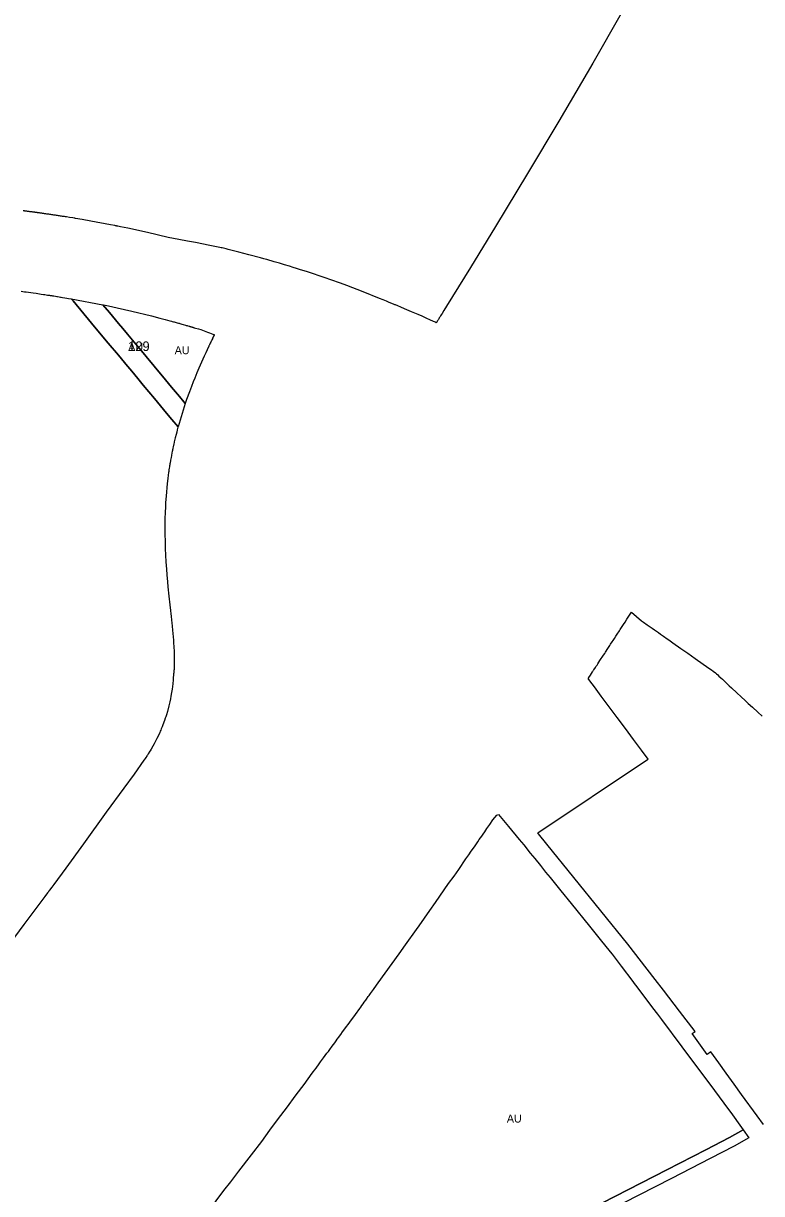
# Model space of a CAD drawing. Extents: x -537068 to -534056, y -1176840 to -1172401.
# Drawn here: x -536541 to -536080, y -1174949 to -1174218 of the extents above; entities that cross this region are included whole.
import ezdxf

# ---------------------------------------------------------------- set-up
doc = ezdxf.new("R2010")
doc.units = 0
for name, color, linetype in [('90710023', 7, 'Continuous'), ('90750013', 7, 'Continuous'), ('90750023', 7, 'Continuous'), ('ID_navrh', 7, 'Continuous')]:
    doc.layers.add(name, color=color, linetype=linetype)

msp = doc.modelspace()

# ---------------------------------------------------------------- linework, layer by layer
at = {"layer": '90710023'}
msp.add_lwpolyline([(-536179.07, -1174955.11), (-536138.87, -1174934.4), (-536114.61, -1174921.9), (-536099.73, -1174914.23), (-536091.18, -1174909.41), (-536087.7, -1174914.34), (-536096.88, -1174919.51), (-536111.86, -1174927.23), (-536136.12, -1174939.73), (-536176.32, -1174960.44)], dxfattribs=at)
at = {"layer": '90750013'}
for points in [[(-536167.39, -1174211.76), (-536185.2, -1174242.92), (-536206.47, -1174279.11), (-536226.04, -1174311.88), (-536245.85, -1174344.89), (-536261.5, -1174370.57), (-536276.47, -1174394.75), (-536278.12, -1174397.41), (-536279.32, -1174399.29), (-536279.8, -1174400.06), (-536280.27, -1174400.82), (-536280.79, -1174401.65), (-536281.05, -1174402.07), (-536281.38, -1174402.6), (-536281.6, -1174402.95), (-536281.78, -1174403.24), (-536282, -1174403.59), (-536282.28, -1174404.03), (-536282.44, -1174404.3), (-536282.64, -1174404.62), (-536282.76, -1174404.8), (-536282.77, -1174404.82), (-536282.78, -1174404.84), (-536282.79, -1174404.85), (-536282.8, -1174404.87), (-536282.83, -1174404.91), (-536282.88, -1174404.99), (-536282.91, -1174405.04), (-536282.91, -1174405.05), (-536282.92, -1174405.05), (-536282.92, -1174405.06), (-536283.5, -1174404.79), (-536283.99, -1174404.56), (-536284.74, -1174404.22), (-536287.03, -1174403.18), (-536288.89, -1174402.34), (-536291.82, -1174401.02), (-536294.29, -1174399.94), (-536298.38, -1174398.15), (-536302.76, -1174396.3), (-536305.03, -1174395.35), (-536307.03, -1174394.52), (-536307.46, -1174394.35), (-536308, -1174394.12), (-536308.4, -1174393.96), (-536308.82, -1174393.78), (-536309.68, -1174393.43), (-536310.21, -1174393.21), (-536310.75, -1174392.99), (-536312.38, -1174392.33), (-536313.99, -1174391.68), (-536316.07, -1174390.85), (-536318.46, -1174389.9), (-536328.56, -1174385.71), (-536338.75, -1174381.78), (-536342.81, -1174380.27), (-536348.81, -1174378.18), (-536352.24, -1174377.01), (-536355.46, -1174375.92), (-536360.21, -1174374.36), (-536363.95, -1174373.15), (-536367.71, -1174371.96), (-536370.22, -1174371.18), (-536372.29, -1174370.52), (-536374.68, -1174369.78), (-536377.82, -1174368.83), (-536380.84, -1174367.93), (-536384.28, -1174366.93), (-536388.73, -1174365.64), (-536389.74, -1174365.36), (-536390.66, -1174365.1), (-536392.72, -1174364.52), (-536400.1, -1174362.55), (-536406.21, -1174360.95), (-536409.68, -1174360.06), (-536412.92, -1174359.26), (-536414.22, -1174358.94), (-536415.89, -1174358.54), (-536416.64, -1174358.36), (-536417.29, -1174358.2), (-536418.11, -1174358.01), (-536424.41, -1174356.74), (-536433.4, -1174354.97), (-536438.38, -1174354.08), (-536443.72, -1174353.14), (-536450.5, -1174351.85), (-536463.41, -1174348.62), (-536475.59, -1174346.07), (-536480.22, -1174345.08), (-536481.74, -1174344.77), (-536482.41, -1174344.63), (-536482.72, -1174344.57), (-536483.35, -1174344.44), (-536483.81, -1174344.35), (-536486.52, -1174343.8), (-536498.74, -1174341.52), (-536504.04, -1174340.59), (-536508.25, -1174339.88), (-536508.8, -1174339.79), (-536508.97, -1174339.77), (-536509.01, -1174339.76), (-536509.03, -1174339.76), (-536509.04, -1174339.75), (-536509.05, -1174339.75), (-536509.06, -1174339.75), (-536509.07, -1174339.75), (-536509.98, -1174339.6), (-536512.13, -1174339.25), (-536513.97, -1174338.96), (-536514.58, -1174338.87), (-536515.19, -1174338.77), (-536515.8, -1174338.68), (-536516.41, -1174338.58), (-536517.03, -1174338.49), (-536517.64, -1174338.4), (-536518.25, -1174338.3), (-536518.86, -1174338.21), (-536519.47, -1174338.12), (-536520.08, -1174338.03), (-536520.69, -1174337.93), (-536521.3, -1174337.84), (-536521.91, -1174337.75), (-536522.52, -1174337.66), (-536523.13, -1174337.57), (-536523.74, -1174337.49), (-536524.35, -1174337.4), (-536524.96, -1174337.31), (-536525.57, -1174337.22), (-536526.18, -1174337.13), (-536526.79, -1174337.05), (-536527.09, -1174337), (-536527.4, -1174336.96), (-536527.7, -1174336.92), (-536528.01, -1174336.88), (-536528.31, -1174336.83), (-536528.62, -1174336.79), (-536528.92, -1174336.75), (-536529.22, -1174336.7), (-536529.53, -1174336.66), (-536529.83, -1174336.62), (-536530.14, -1174336.58), (-536530.44, -1174336.54), (-536530.75, -1174336.49), (-536531.05, -1174336.45), (-536531.35, -1174336.41), (-536531.66, -1174336.37), (-536531.96, -1174336.33), (-536532.26, -1174336.28), (-536532.57, -1174336.24), (-536532.87, -1174336.2), (-536533.18, -1174336.16), (-536533.48, -1174336.12), (-536533.78, -1174336.08), (-536534.09, -1174336.04), (-536534.39, -1174335.99), (-536534.69, -1174335.95), (-536535, -1174335.91), (-536535.3, -1174335.87), (-536535.6, -1174335.83), (-536535.91, -1174335.79), (-536536.21, -1174335.75), (-536536.51, -1174335.71), (-536536.82, -1174335.67), (-536537.12, -1174335.63), (-536537.42, -1174335.59), (-536537.73, -1174335.55), (-536538.03, -1174335.51), (-536538.33, -1174335.47), (-536538.63, -1174335.43), (-536538.94, -1174335.39), (-536539.24, -1174335.35), (-536539.54, -1174335.31), (-536539.85, -1174335.27), (-536540.15, -1174335.23), (-536540.45, -1174335.19), (-536540.75, -1174335.15), (-536541.06, -1174335.11)], [(-536542.24, -1174385.39), (-536540.21, -1174385.66), (-536539.04, -1174385.82), (-536537.59, -1174386.02), (-536536.14, -1174386.22), (-536534.69, -1174386.43), (-536532.95, -1174386.67), (-536531.8, -1174386.84), (-536529.78, -1174387.14), (-536528.33, -1174387.35), (-536527.47, -1174387.48), (-536526.6, -1174387.61), (-536525.74, -1174387.74), (-536525.17, -1174387.82), (-536524.59, -1174387.91), (-536524.02, -1174388), (-536523.16, -1174388.13), (-536522.58, -1174388.22), (-536521.72, -1174388.36), (-536520.86, -1174388.49), (-536520, -1174388.63), (-536519.43, -1174388.72), (-536518.57, -1174388.86), (-536517.72, -1174389), (-536517.14, -1174389.09), (-536516.34, -1174389.22), (-536514.86, -1174389.46), (-536513.65, -1174389.66), (-536512.58, -1174389.85), (-536510.97, -1174390.13), (-536509.84, -1174391.48), (-536503.16, -1174399.47), (-536495.28, -1174408.89), (-536487.81, -1174417.82), (-536481.51, -1174425.34), (-536477.7, -1174429.89), (-536476.74, -1174431.03), (-536473.17, -1174435.33), (-536469.4, -1174439.87), (-536465.96, -1174444.02), (-536462.53, -1174448.14), (-536458.89, -1174452.51), (-536451.43, -1174461.48), (-536448.09, -1174465.49), (-536444.22, -1174470.15), (-536444.29, -1174470.42), (-536444.7, -1174471.91), (-536445.09, -1174473.42), (-536445.48, -1174474.94), (-536445.99, -1174476.98), (-536446.6, -1174479.57), (-536446.96, -1174481.14), (-536447.06, -1174481.6), (-536447.27, -1174482.55), (-536447.44, -1174483.34), (-536447.48, -1174483.54), (-536447.5, -1174483.64), (-536447.53, -1174483.76), (-536447.54, -1174483.83), (-536447.56, -1174483.92), (-536447.57, -1174483.97), (-536447.59, -1174484.05), (-536447.6, -1174484.11), (-536447.62, -1174484.19), (-536447.63, -1174484.24), (-536447.65, -1174484.33), (-536447.66, -1174484.39), (-536447.68, -1174484.5), (-536447.7, -1174484.59), (-536447.71, -1174484.65), (-536447.72, -1174484.7), (-536447.73, -1174484.73), (-536447.73, -1174484.74), (-536447.73, -1174484.75), (-536447.74, -1174484.77), (-536447.74, -1174484.78), (-536447.76, -1174484.86), (-536447.78, -1174484.97), (-536447.9, -1174485.53), (-536448.06, -1174486.4), (-536448.4, -1174488.1), (-536448.6, -1174489.21), (-536448.92, -1174490.92), (-536449.25, -1174492.83), (-536449.25, -1174492.87), (-536449.26, -1174492.91), (-536449.26, -1174492.93), (-536449.26, -1174492.94), (-536449.27, -1174492.95), (-536449.28, -1174493.06), (-536449.29, -1174493.07), (-536449.29, -1174493.09), (-536449.29, -1174493.1), (-536449.29, -1174493.11), (-536449.29, -1174493.12), (-536449.3, -1174493.13), (-536449.3, -1174493.15), (-536449.3, -1174493.16), (-536449.3, -1174493.17), (-536449.31, -1174493.22), (-536449.32, -1174493.25), (-536449.32, -1174493.28), (-536449.32, -1174493.29), (-536449.33, -1174493.34), (-536449.33, -1174493.35), (-536449.33, -1174493.36), (-536449.34, -1174493.37), (-536449.34, -1174493.38), (-536449.34, -1174493.39), (-536449.34, -1174493.4), (-536449.34, -1174493.41), (-536449.35, -1174493.45), (-536449.35, -1174493.46), (-536449.36, -1174493.51), (-536449.37, -1174493.59), (-536449.38, -1174493.66), (-536449.4, -1174493.77), (-536449.44, -1174493.97), (-536449.48, -1174494.26), (-536449.54, -1174494.59), (-536449.58, -1174494.88), (-536449.63, -1174495.19), (-536449.75, -1174495.96), (-536449.9, -1174496.98), (-536450.06, -1174498.03), (-536450.16, -1174498.73), (-536450.38, -1174500.38), (-536450.65, -1174502.44), (-536451.02, -1174505.61), (-536451.29, -1174508.22), (-536451.53, -1174510.81), (-536451.75, -1174513.36), (-536452.02, -1174517.4), (-536452.16, -1174519.88), (-536452.33, -1174523.79), (-536452.43, -1174527.15), (-536452.5, -1174532.78), (-536452.48, -1174536.44), (-536452.35, -1174542.66), (-536452.23, -1174546.1), (-536452.04, -1174550.3), (-536451.8, -1174554.37), (-536451.47, -1174559.05), (-536451.2, -1174562.49), (-536450.82, -1174566.91), (-536450.52, -1174570.12), (-536449.94, -1174575.9), (-536449.37, -1174581.34), (-536448.98, -1174584.97), (-536448.76, -1174587.01), (-536448.61, -1174588.44), (-536448.34, -1174590.95), (-536448.17, -1174592.58), (-536447.96, -1174594.69), (-536447.71, -1174597.24), (-536447.53, -1174599.2), (-536447.34, -1174601.34), (-536447.17, -1174603.39), (-536447.01, -1174605.57), (-536446.9, -1174607.24), (-536446.83, -1174608.4), (-536446.75, -1174609.77), (-536446.69, -1174611.08), (-536446.65, -1174612.34), (-536446.61, -1174613.55), (-536446.59, -1174614.72), (-536446.57, -1174615.98), (-536446.58, -1174617.47), (-536446.58, -1174617.76), (-536446.59, -1174618.18), (-536446.6, -1174618.45), (-536446.6, -1174618.72), (-536446.62, -1174619.25), (-536446.63, -1174619.64), (-536446.65, -1174620.02), (-536446.67, -1174620.5), (-536446.69, -1174620.98), (-536446.71, -1174621.32), (-536446.74, -1174621.65), (-536446.75, -1174621.87), (-536446.77, -1174622.08), (-536446.78, -1174622.29), (-536446.81, -1174622.59), (-536446.83, -1174622.89), (-536446.85, -1174623.08), (-536446.92, -1174623.71), (-536446.93, -1174623.79), (-536446.94, -1174623.91), (-536446.94, -1174623.94), (-536446.95, -1174623.98), (-536446.95, -1174623.99), (-536446.95, -1174624), (-536446.95, -1174624.01), (-536446.95, -1174624.02), (-536446.95, -1174624.03), (-536446.95, -1174624.04), (-536446.96, -1174624.05), (-536446.96, -1174624.06), (-536446.96, -1174624.07), (-536446.96, -1174624.08), (-536446.96, -1174624.11), (-536446.96, -1174624.12), (-536446.97, -1174624.14), (-536446.97, -1174624.17), (-536446.98, -1174624.21), (-536446.98, -1174624.26), (-536446.98, -1174624.28), (-536446.99, -1174624.33), (-536447.04, -1174624.72), (-536447.07, -1174624.96), (-536447.15, -1174625.52), (-536447.22, -1174626.58), (-536447.32, -1174628.16), (-536447.54, -1174630.65), (-536447.97, -1174634.02), (-536448.26, -1174636.09), (-536448.64, -1174638.38), (-536448.99, -1174640.13), (-536449.34, -1174641.85), (-536449.92, -1174644.38), (-536450.88, -1174647.95), (-536451.52, -1174650.08), (-536451.93, -1174651.39), (-536452.21, -1174652.22), (-536452.72, -1174653.7), (-536453.67, -1174656.3), (-536453.91, -1174656.9), (-536454.16, -1174657.54), (-536454.33, -1174657.95), (-536454.7, -1174658.86), (-536455.01, -1174659.61), (-536455.33, -1174660.34), (-536455.65, -1174661.05), (-536455.91, -1174661.68), (-536457.41, -1174664.84), (-536459.2, -1174668.27), (-536459.91, -1174669.56), (-536461.07, -1174671.55), (-536461.7, -1174672.59), (-536461.84, -1174672.83), (-536462.79, -1174674.34), (-536462.9, -1174674.51), (-536463.37, -1174675.23), (-536463.47, -1174675.39), (-536463.5, -1174675.42), (-536463.51, -1174675.44), (-536463.59, -1174675.57), (-536463.63, -1174675.62), (-536463.75, -1174675.8), (-536464.35, -1174676.7), (-536464.52, -1174676.95), (-536464.62, -1174677.1), (-536465.57, -1174678.46), (-536471.74, -1174687.11), (-536478.01, -1174695.81), (-536489.05, -1174710.98), (-536503.23, -1174730.7), (-536514.37, -1174745.87), (-536521.87, -1174756.07), (-536523.15, -1174757.8), (-536524.44, -1174759.54), (-536524.56, -1174759.7), (-536524.74, -1174759.94), (-536524.78, -1174760), (-536524.81, -1174760.04), (-536524.82, -1174760.05), (-536524.82, -1174760.06), (-536524.83, -1174760.06), (-536524.83, -1174760.07), (-536524.84, -1174760.08), (-536524.85, -1174760.09), (-536524.86, -1174760.1), (-536524.86, -1174760.11), (-536524.87, -1174760.11), (-536524.87, -1174760.12), (-536524.88, -1174760.14), (-536524.89, -1174760.15), (-536524.9, -1174760.17), (-536524.93, -1174760.2), (-536524.95, -1174760.23), (-536524.96, -1174760.24), (-536524.99, -1174760.27), (-536525.03, -1174760.34), (-536525.06, -1174760.38), (-536525.09, -1174760.41), (-536525.1, -1174760.43), (-536525.12, -1174760.45), (-536525.14, -1174760.49), (-536525.17, -1174760.53), (-536525.2, -1174760.56), (-536525.22, -1174760.59), (-536525.29, -1174760.69), (-536525.32, -1174760.72), (-536525.37, -1174760.79), (-536525.44, -1174760.88), (-536525.56, -1174761.05), (-536525.68, -1174761.21), (-536527.39, -1174763.63), (-536540.49, -1174781.02), (-536546.4, -1174789.03)], [(-536078.52, -1174906.12), (-536082.49, -1174900.65), (-536092.2, -1174887.28), (-536096.81, -1174880.92), (-536101.82, -1174874.01), (-536106.55, -1174867.48), (-536111.47, -1174860.69), (-536113.67, -1174862.22), (-536123.18, -1174849.17), (-536121.32, -1174847.86), (-536131.09, -1174835.14), (-536141.08, -1174822.15), (-536146.22, -1174815.46), (-536151.19, -1174809), (-536163.27, -1174793.29), (-536213.79, -1174730.95), (-536219.11, -1174724.39), (-536219.53, -1174723.87), (-536152.25, -1174678.88), (-536150.59, -1174677.77), (-536154.85, -1174672.05), (-536159.67, -1174665.58), (-536164.83, -1174658.65), (-536169.92, -1174651.82), (-536174.9, -1174645.14), (-536179.96, -1174638.35), (-536184.2, -1174632.66), (-536187, -1174628.9), (-536188.1, -1174627.42), (-536187.87, -1174627.06), (-536187.29, -1174626.2), (-536187.05, -1174625.84), (-536186.67, -1174625.25), (-536185.3, -1174623.16), (-536185.09, -1174622.85), (-536184.9, -1174622.57), (-536184.7, -1174622.26), (-536184.47, -1174621.9), (-536184.15, -1174621.43), (-536183.9, -1174621.04), (-536183.59, -1174620.56), (-536183.18, -1174619.95), (-536182.54, -1174618.98), (-536182.04, -1174618.24), (-536181.41, -1174617.25), (-536180.7, -1174616.18), (-536179.9, -1174614.97), (-536179.23, -1174613.94), (-536178.42, -1174612.69), (-536177.76, -1174611.69), (-536177.24, -1174610.91), (-536175.77, -1174608.64), (-536175.32, -1174607.98), (-536174.89, -1174607.3), (-536174.53, -1174606.75), (-536174.02, -1174605.97), (-536173.08, -1174604.53), (-536172.46, -1174603.58), (-536171.61, -1174602.29), (-536170.74, -1174600.94), (-536169.96, -1174599.75), (-536169.51, -1174599.07), (-536168.91, -1174598.14), (-536168.51, -1174597.52), (-536168.01, -1174596.73), (-536167.18, -1174595.51), (-536165.99, -1174593.67), (-536165.06, -1174592.19), (-536163.84, -1174590.35), (-536162.61, -1174588.43), (-536161.02, -1174586), (-536154.69, -1174591.35), (-536153.43, -1174592.24), (-536151.14, -1174593.83), (-536148.12, -1174595.95), (-536146.68, -1174596.96), (-536144.22, -1174598.71), (-536142.93, -1174599.59), (-536140.95, -1174601), (-536138.82, -1174602.51), (-536137.66, -1174603.31), (-536135.2, -1174605.08), (-536130.17, -1174608.6), (-536125.9, -1174611.57), (-536121.16, -1174614.93), (-536116.14, -1174618.45), (-536112.12, -1174621.27), (-536111.04, -1174622.04), (-536110.05, -1174622.73), (-536108.61, -1174623.75), (-536107.87, -1174624.42), (-536107.18, -1174625.1), (-536106.35, -1174625.83), (-536105.3, -1174626.86), (-536104.24, -1174627.86), (-536103.19, -1174628.87), (-536100.95, -1174630.96), (-536099.93, -1174631.93), (-536098.56, -1174633.22), (-536095.25, -1174636.35), (-536092.56, -1174638.79), (-536089.94, -1174641.13), (-536088.04, -1174642.95), (-536085.41, -1174645.3), (-536082.01, -1174648.5), (-536079.3, -1174650.88)], [(-536425.14, -1174960.28), (-536415.59, -1174947.33), (-536411.22, -1174941.83), (-536406.2, -1174935.2), (-536398.28, -1174925), (-536391.96, -1174916.59), (-536386.87, -1174909.63), (-536381.45, -1174902.35), (-536376.43, -1174895.8), (-536370.44, -1174887.54), (-536365.51, -1174880.99), (-536360.38, -1174874.04), (-536359.54, -1174872.92), (-536358.91, -1174872.07), (-536358.05, -1174870.93), (-536357.54, -1174870.19), (-536356.53, -1174868.82), (-536355.24, -1174867), (-536353.3, -1174864.49), (-536351.21, -1174861.58), (-536350.3, -1174860.39), (-536349.51, -1174859.28), (-536347.98, -1174857.21), (-536347.15, -1174856.04), (-536346.36, -1174854.99), (-536345.53, -1174853.83), (-536344.78, -1174852.84), (-536343.77, -1174851.45), (-536343.34, -1174850.86), (-536342.53, -1174849.75), (-536341.42, -1174848.25), (-536338.79, -1174844.63), (-536338.16, -1174843.75), (-536337.44, -1174842.77), (-536336.55, -1174841.54), (-536335.68, -1174840.44), (-536333.49, -1174837.29), (-536330.7, -1174833.51), (-536330.14, -1174832.7), (-536329.35, -1174831.62), (-536328.7, -1174830.71), (-536327.95, -1174829.68), (-536327.04, -1174828.44), (-536326.49, -1174827.68), (-536325.38, -1174826.13), (-536324.93, -1174825.53), (-536324.46, -1174824.88), (-536323.96, -1174824.17), (-536323.37, -1174823.37), (-536322.8, -1174822.56), (-536322.11, -1174821.6), (-536321.7, -1174821.05), (-536319.22, -1174817.54), (-536306.21, -1174799.45), (-536302.21, -1174793.69), (-536295.37, -1174784.2), (-536293.67, -1174781.82), (-536286.98, -1174772.33), (-536283.4, -1174767.33), (-536275.22, -1174755.48), (-536271.83, -1174750.79), (-536268.95, -1174746.62), (-536264.46, -1174740.15), (-536262.62, -1174737.5), (-536261.08, -1174735.31), (-536259.12, -1174732.46), (-536256.98, -1174729.37), (-536256.05, -1174728.03), (-536255.36, -1174727), (-536254.55, -1174725.87), (-536253.72, -1174724.65), (-536252.65, -1174723.1), (-536251.29, -1174721.15), (-536249.49, -1174718.5), (-536247.51, -1174715.63), (-536245.11, -1174712.76), (-536244.02, -1174712.25), (-536237.73, -1174719.92), (-536231.13, -1174727.97), (-536228.31, -1174731.41), (-536224.24, -1174736.43), (-536221.47, -1174739.85), (-536217.9, -1174744.27), (-536214.63, -1174748.31), (-536211.88, -1174751.71), (-536205.19, -1174759.98), (-536198.75, -1174767.94), (-536187.28, -1174782.1), (-536180.56, -1174790.4), (-536174.29, -1174798.14), (-536173.08, -1174799.63), (-536167.37, -1174807.22), (-536160.19, -1174816.77), (-536159.25, -1174818.01), (-536158.45, -1174819.07), (-536153.38, -1174825.82), (-536147.84, -1174833.18), (-536144.81, -1174837.2), (-536142.35, -1174840.47), (-536129.48, -1174857.58), (-536121.6, -1174868.06), (-536119.51, -1174870.86), (-536109.09, -1174884.87), (-536103.25, -1174892.72), (-536097.82, -1174900.02), (-536093.29, -1174906.43), (-536091.18, -1174909.41), (-536099.73, -1174914.23), (-536114.61, -1174921.9), (-536138.87, -1174934.4), (-536179.07, -1174955.11)]]:
    msp.add_lwpolyline(points, dxfattribs=at)
msp.add_lwpolyline([(-536491.16, -1174393.88), (-536490.84, -1174393.94), (-536487.7, -1174394.6), (-536482.28, -1174395.75), (-536473.13, -1174397.82), (-536460.81, -1174400.81), (-536455.68, -1174402.13), (-536452.2, -1174403.06), (-536449.26, -1174403.84), (-536448.31, -1174404.11), (-536447.86, -1174404.23), (-536447.13, -1174404.43), (-536446.75, -1174404.53), (-536444.75, -1174405.09), (-536444.04, -1174405.29), (-536443.61, -1174405.41), (-536443.08, -1174405.56), (-536441.94, -1174405.88), (-536440.93, -1174406.17), (-536439.6, -1174406.55), (-536439.11, -1174406.69), (-536438.63, -1174406.83), (-536438.08, -1174406.99), (-536437.37, -1174407.2), (-536437.23, -1174407.24), (-536437.07, -1174407.28), (-536436.91, -1174407.33), (-536436.73, -1174407.38), (-536436.52, -1174407.44), (-536436.35, -1174407.49), (-536436.14, -1174407.55), (-536436, -1174407.6), (-536435.85, -1174407.64), (-536435.71, -1174407.68), (-536435.61, -1174407.71), (-536435.54, -1174407.73), (-536435.45, -1174407.76), (-536435.36, -1174407.79), (-536435.31, -1174407.8), (-536435.18, -1174407.84), (-536435.07, -1174407.87), (-536434.95, -1174407.91), (-536434.73, -1174407.97), (-536434.45, -1174408.05), (-536434.09, -1174408.16), (-536433.26, -1174408.41), (-536431.52, -1174408.9), (-536430, -1174409.39), (-536428.97, -1174409.76), (-536427.9, -1174410.15), (-536425.85, -1174410.9), (-536424.58, -1174411.36), (-536422.54, -1174412.11), (-536421.54, -1174412.48), (-536421.59, -1174412.6), (-536421.74, -1174412.9), (-536422.03, -1174413.51), (-536422.33, -1174414.13), (-536422.63, -1174414.75), (-536422.78, -1174415.06), (-536423.08, -1174415.69), (-536423.39, -1174416.33), (-536423.54, -1174416.64), (-536423.84, -1174417.28), (-536424.15, -1174417.93), (-536424.3, -1174418.25), (-536424.61, -1174418.91), (-536424.77, -1174419.23), (-536424.92, -1174419.56), (-536425.08, -1174419.89), (-536425.23, -1174420.22), (-536426.96, -1174423.95), (-536427.91, -1174426.04), (-536429.52, -1174429.63), (-536431.16, -1174433.39), (-536432.46, -1174436.46), (-536433.76, -1174439.61), (-536434.73, -1174442.03), (-536435.86, -1174444.91), (-536437.13, -1174448.29), (-536438.86, -1174453.07), (-536439.72, -1174455.61), (-536440.62, -1174454.52), (-536443.37, -1174451.21), (-536448.28, -1174445.29), (-536453.87, -1174438.55), (-536456.15, -1174435.81), (-536459.11, -1174432.25), (-536464.18, -1174426.13), (-536467.05, -1174422.67), (-536469.54, -1174419.69), (-536475.89, -1174412.11), (-536478.81, -1174408.63), (-536481.33, -1174405.62), (-536487.08, -1174398.75)], close=True, dxfattribs=at)
at = {"layer": '90750023'}
msp.add_lwpolyline([(-536510.97, -1174390.13), (-536491.16, -1174393.88), (-536487.08, -1174398.75), (-536481.33, -1174405.62), (-536478.81, -1174408.63), (-536475.89, -1174412.11), (-536469.54, -1174419.69), (-536467.05, -1174422.67), (-536464.18, -1174426.13), (-536459.11, -1174432.25), (-536456.15, -1174435.81), (-536453.87, -1174438.55), (-536448.28, -1174445.29), (-536443.37, -1174451.21), (-536440.62, -1174454.52), (-536439.72, -1174455.61), (-536444.22, -1174470.15), (-536448.09, -1174465.49), (-536451.43, -1174461.48), (-536458.89, -1174452.51), (-536462.53, -1174448.14), (-536465.96, -1174444.02), (-536469.4, -1174439.87), (-536473.17, -1174435.33), (-536476.74, -1174431.03), (-536477.7, -1174429.89), (-536481.51, -1174425.34), (-536487.81, -1174417.82), (-536495.28, -1174408.89), (-536503.16, -1174399.47), (-536509.84, -1174391.48)], close=True, dxfattribs=at)

# ---------------------------------------------------------------- texts
at = {"layer": '90750013'}
for rotation, p in [(360, (-536446.33, -1174424.75)), (0, (-536238.86, -1174904.84))]:
    msp.add_text('AU', height=5, rotation=rotation, dxfattribs=at).set_placement(p)
at = {"layer": '90750023'}
msp.add_text('AU', height=5, rotation=0, dxfattribs=at).set_placement((-536475.35, -1174422.74))
at = {"layer": 'ID_navrh'}
msp.add_text('129', height=6, rotation=0, dxfattribs=at).set_placement((-536475.35, -1174422.74))

doc.saveas('drawing.dxf')
